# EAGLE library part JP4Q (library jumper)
JUMPER
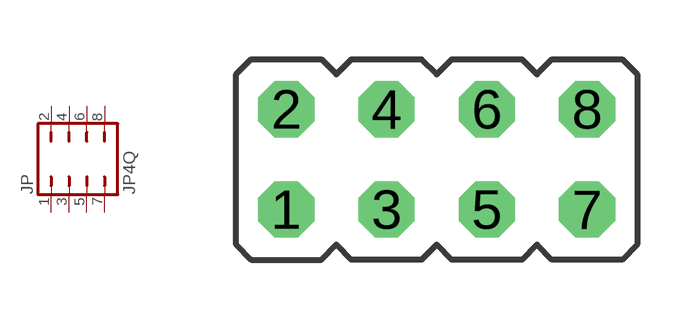
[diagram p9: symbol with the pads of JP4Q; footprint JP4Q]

Designator prefix JP

## JP4Q  [JP4Q]
1  1  pas
2  2  pas
3  3  pas
4  4  pas
5  5  pas
6  6  pas
7  7  pas
8  8  pas

## Footprint JP4Q (pad centres in mm)
JUMPER
drill 0.914 octagon: 1 -3.81,-1.27; 2 -3.81,1.27; 3 -1.27,-1.27; 4 -1.27,1.27; 5 1.27,-1.27; 6 1.27,1.27; 7 3.81,-1.27; 8 3.81,1.27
